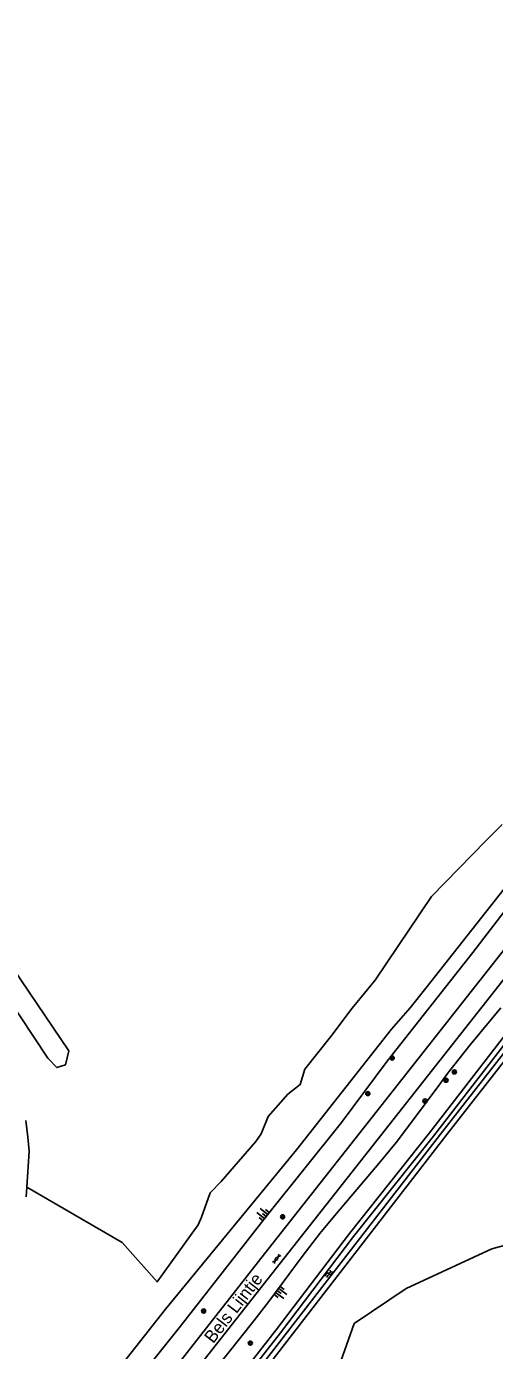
# Model space of a CAD drawing. Extents: x 126000 to 131009, y 393000 to 395500.
# Drawn here: x 130043.4 to 130135.4, y 393932.5 to 394193.1 of the extents above; entities that cross this region are included whole.
import ezdxf

# ---------------------------------------------------------------- set-up
doc = ezdxf.new("R2010")
doc.units = 0
for name, color, linetype in [('gg-anno-openbare ruimte label', 7, 'Continuous'), ('gg-knt-BGT kruinlijn', 7, 'Continuous'), ('gg-knt-bovenkant onderkant talud', 7, 'Continuous'), ('gt-grn-groengrens', 7, 'Continuous'), ('gt-symb-boom', 7, 'Continuous'), ('gt-symb-gesloten verharding', 7, 'Continuous'), ('gt-symb-talud symbool', 7, 'Continuous'), ('gt-symb-watersymbool', 7, 'Continuous'), ('gx-grn-maaiveld', 7, 'Continuous')]:
    doc.layers.add(name, color=color, linetype=linetype)

# ---------------------------------------------------------------- blocks, each defined once
blk = doc.blocks.new('gt0-TALUD_1')
at = {"layer": 'gt-symb-talud symbool'}
for p, q in [((-1, -1), (-1, 0)), ((-0.5, -2), (-0.5, 0)), ((0, -1), (0, 0)), ((0.5, -2), (0.5, 0)), ((1, -1), (1, 0))]:
    blk.add_line(p, q, dxfattribs=at)
blk = doc.blocks.new('gt0-GESVH1')
at = {"layer": 'gt-symb-gesloten verharding'}
for p, q in [((-0.99, -0.26), (0.01, 0.24)), ((0.01, -0.26), (-0.99, 0.24)), ((0.01, 0.24), (1.01, -0.26)), ((1.01, 0.24), (0.01, -0.26))]:
    blk.add_line(p, q, dxfattribs=at)
blk = doc.blocks.new('gt0-BOOM')
at = {"layer": 'gt-symb-boom'}
for radius in [0.4, 0.2]:
    blk.add_circle((0, 0), radius, dxfattribs=at)
blk = doc.blocks.new('gt0-WA')
at = {"layer": 'gt-symb-watersymbool'}
for centre, start, end in [((-0.32, 0.02), 28.0725, 151.9275), ((0.43, 0.42), 208.0725, 331.9275), ((-0.32, -0.43), 28.0725, 151.9275), ((0.43, -0.03), 208.0725, 331.9275)]:
    blk.add_arc(centre, 0.425, start, end, dxfattribs=at)

msp = doc.modelspace()

# ---------------------------------------------------------------- linework, layer by layer
at = {"layer": 'gg-knt-BGT kruinlijn'}
for points in [[(130138.09, 394019.9), (130131.16, 394010.84), (130114.29, 393989.45), (130105.32, 393977.42), (130090.8, 393959.23), (130073.42, 393937.01), (130065.02, 393926.5), (130055.46, 393914.65), (130049.86, 393907.6), (130045.54, 393902.09), (130044.1, 393899.99)], [(130057.95, 393899.52), (130059.66, 393902.02), (130061.58, 393903.28), (130064, 393906.45), (130066.36, 393909.68), (130072.72, 393918.67), (130075.08, 393921.9), (130078.12, 393925.86), (130088.1, 393938.37), (130091.01, 393942.21), (130097.57, 393951.04), (130101.09, 393955.54), (130103.63, 393958.63), (130112.69, 393969.31), (130116.06, 393973.49), (130119.12, 393977.45), (130124.5, 393984.66), (130126.18, 393987.07), (130130.65, 393992.68), (130136.69, 394000)]]:
    msp.add_lwpolyline(points, dxfattribs=at)
at = {"layer": 'gg-knt-bovenkant onderkant talud'}
for points in [[(130137.33, 394023.36), (130121.89, 394003.84), (130118.81, 394000)], [(130118.81, 394000), (130115.15, 393995.76), (130096.51, 393972.04), (130070.73, 393940.7), (130050.77, 393915.34), (130036.66, 393897.81)]]:
    msp.add_lwpolyline(points, dxfattribs=at)
at = {"layer": 'gt-grn-groengrens'}
msp.add_lwpolyline([(130105.17, 393930.42), (130107.85, 393937.85), (130118.05, 393944.74), (130134.86, 393952.53), (130150.87, 393956.91), (130189.33, 393963), (130211.69, 393966.54), (130229.51, 393964.13), (130235.97, 393964.67)], dxfattribs=at)
at = {"layer": 'gx-grn-maaiveld'}
msp.add_line((130043.44, 393964.69), (130043.32, 393962.81), dxfattribs=at)
for points in [[(130045.18, 393888.61), (130051.7, 393896.86), (130094.04, 393950.74), (130218.22, 394108.45), (130343.52, 394267.78), (130352.02, 394278.84), (130359.87, 394289.49), (130367.63, 394300.9), (130375.09, 394312.48), (130382.3, 394324.57), (130388.46, 394335.64), (130391.13, 394340.65), (130392.06, 394342.07)], [(130043.44, 393964.69), (130062.2, 393953.79), (130069.07, 393946.05), (130077.17, 393957.3), (130077.81, 393958.78), (130079.5, 393963.54), (130081.67, 393965.82), (130088.49, 393973.65), (130089.55, 393975.18), (130090.88, 393978.57), (130094.79, 393983.01), (130097.23, 393984.86), (130098.12, 393987.93), (130103.26, 393994.34), (130107.44, 393999.89), (130111.94, 394005.4), (130123.05, 394021.85), (130133.74, 394032.81), (130136.91, 394036.04)], [(130026.03, 394024.08), (130028.15, 394024.87), (130029.74, 394023.94), (130051.7, 393991.53), (130051.04, 393988.75), (130049.32, 393988.23), (130047.6, 393990.08), (130025.77, 394023.02), (130026.03, 394024.08)], [(130043.52, 393892.12), (130053.33, 393904.54), (130090.91, 393952.46), (130139.38, 394014.01)], [(130144.2, 394000.61), (130139.77, 393994.95), (130137.91, 393991.89), (130125.28, 393975.68), (130077.89, 393914.43), (130064.19, 393896.82), (130063.67, 393896.63), (130063.34, 393896.99), (130063.5, 393897.61), (130074.95, 393912.6), (130093.31, 393935.99), (130107.66, 393954.98), (130123.41, 393974.74), (130139.93, 393996.11), (130142.64, 393999.39)], [(130064.07, 393895.5), (130064.02, 393895.45), (130062.85, 393896.23), (130062.06, 393898.23), (130062.78, 393899.24), (130074.16, 393913.21), (130092.51, 393936.6), (130106.87, 393955.59), (130122.62, 393975.36), (130139.15, 393996.73), (130141.85, 394000)], [(130064.07, 393895.5), (130064.71, 393896.05), (130078.68, 393913.81), (130126.07, 393975.06), (130138.73, 393991.32), (130140.6, 393994.38), (130144.99, 394000)], [(130043.44, 393964.69), (130043.91, 393971.76), (130043.62, 393974.52), (130043.28, 393977.79)]]:
    msp.add_lwpolyline(points, dxfattribs=at)

# ---------------------------------------------------------------- block references
at = {"layer": 'gt-symb-boom'}
for p in [(130115.29, 393990.1), (130127.53, 393987.36), (130125.89, 393985.72), (130110.5, 393983.1), (130121.75, 393981.65), (130093.75, 393958.84), (130078.2, 393940.3), (130087.4, 393934)]:
    msp.add_blockref('gt0-BOOM', p, dxfattribs=at)
at = {"layer": 'gt-symb-gesloten verharding', "rotation": 51.82346240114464}
msp.add_blockref('gt0-GESVH1', (130092.56, 393950.58), dxfattribs=at)
at = {"layer": 'gt-symb-talud symbool'}
for p, xscale, yscale, rotation in [((130090.57, 393958.86), 0.9999864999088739, 0.9999864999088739, -128.4629470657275), ((130092.68, 393944.37), 1.000600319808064, 1.0006003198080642, 53.08429322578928)]:
    msp.add_blockref('gt0-TALUD_1', p, dxfattribs=dict(at, xscale=xscale, yscale=yscale, rotation=rotation))
at = {"layer": 'gt-symb-watersymbool', "rotation": 52.27073010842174}
msp.add_blockref('gt0-WA', (130102.8, 393947.57), dxfattribs=at)

# ---------------------------------------------------------------- texts
at = {"layer": 'gg-anno-openbare ruimte label'}
msp.add_text('Bels Lijntje', height=2.5, rotation=52.3, dxfattribs=at).set_placement((130080.1, 393933.78))

doc.saveas('drawing.dxf')
